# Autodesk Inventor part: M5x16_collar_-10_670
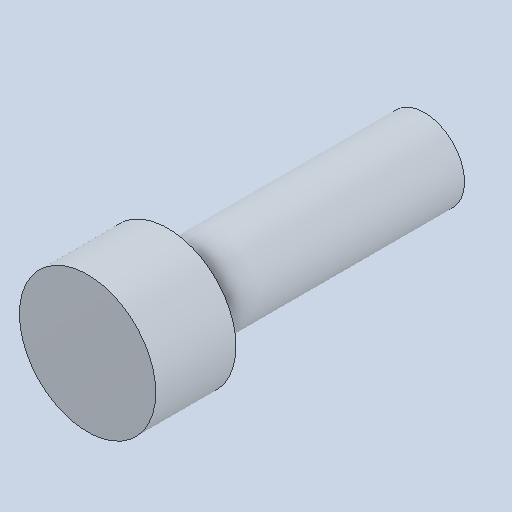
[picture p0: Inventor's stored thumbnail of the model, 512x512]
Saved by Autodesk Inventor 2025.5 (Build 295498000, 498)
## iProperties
Created: 2026-10
Part Number: M5x16_collar_-10_670
Material: Genérico
Document SubType Name: Modeling
Designer: Luis M
Density: 1 g/cm^3
Appearance: Valor por defecto
Author: Luis M
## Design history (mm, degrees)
feature "Base1"
node "Sólido1"
